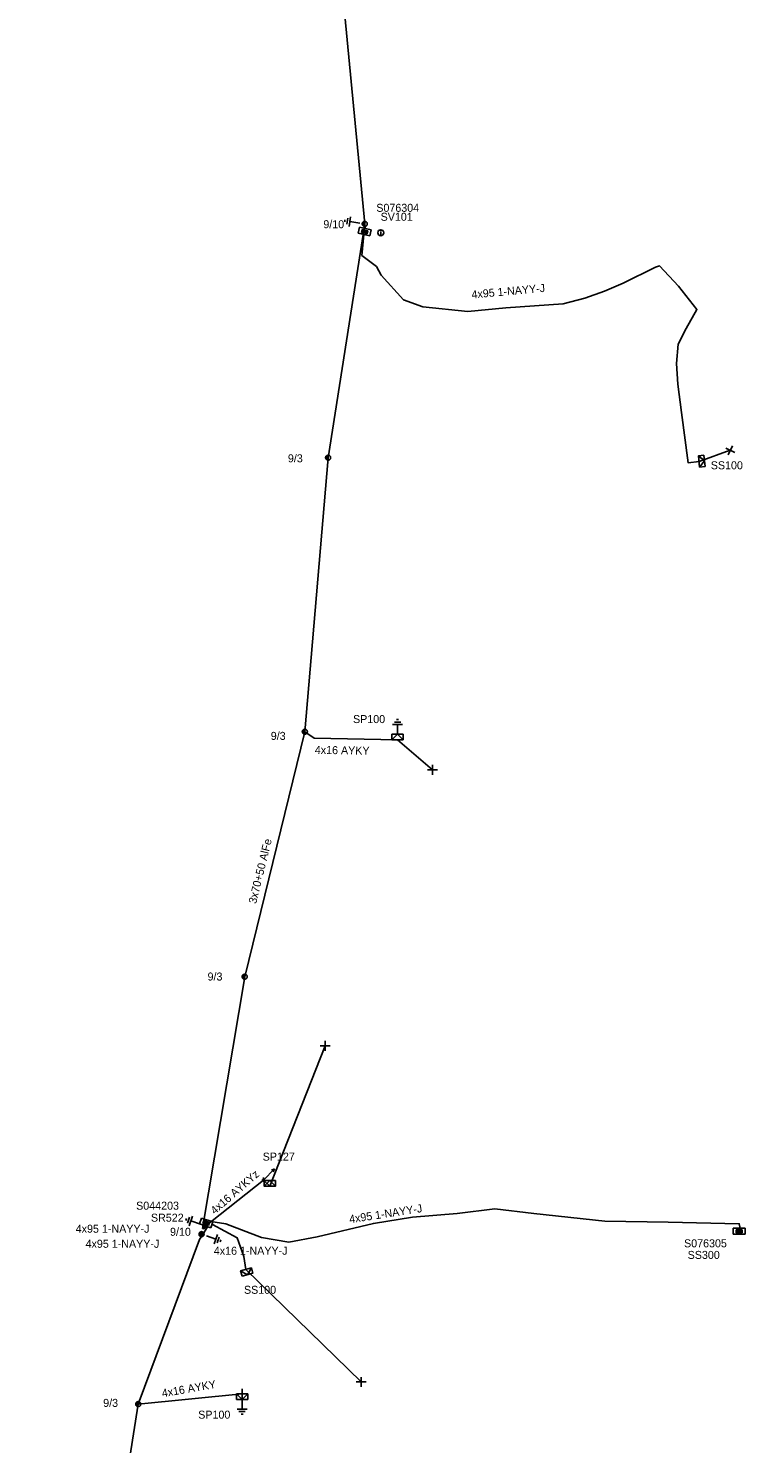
# Model space of a CAD drawing. Extents: x -717562 to -713845, y -1151196 to -1143903.
# Drawn here: x -714115 to -714025.6, y -1146849.6 to -1146672.7 of the extents above; entities that cross this region are included whole.
import ezdxf

# ---------------------------------------------------------------- set-up
doc = ezdxf.new("R2010")
doc.units = 0
for name, color, linetype in [('Vrstva 1', 7, 'Continuous'), ('Vrstva 10', 7, 'Continuous'), ('Vrstva 12', 7, 'Continuous'), ('Vrstva 13', 7, 'Continuous'), ('Vrstva 14', 7, 'Continuous'), ('Vrstva 15', 7, 'Continuous'), ('Vrstva 2', 7, 'Continuous'), ('Vrstva 28', 7, 'Continuous'), ('Vrstva 29', 7, 'Continuous'), ('Vrstva 30', 7, 'Continuous'), ('Vrstva 31', 7, 'Continuous'), ('Vrstva 33', 7, 'Continuous'), ('Vrstva 34', 7, 'Continuous'), ('Vrstva 36', 7, 'Continuous'), ('Vrstva 5', 7, 'Continuous'), ('Vrstva 52', 7, 'Continuous'), ('Vrstva 54', 7, 'Continuous'), ('Vrstva 55', 7, 'Continuous'), ('Vrstva 59', 7, 'Continuous'), ('Vrstva 6', 7, 'Continuous'), ('Vrstva 8', 7, 'Continuous'), ('Vrstva 9', 7, 'Continuous')]:
    doc.layers.add(name, color=color, linetype=linetype)

# ---------------------------------------------------------------- blocks, each defined once
blk = doc.blocks.new('NN440')
at = {"layer": 'Vrstva 2'}
for points in [[(0.63, 0), (0.63, 0.06), (0.62, 0.13), (0.6, 0.19), (0.58, 0.25), (0.55, 0.31), (0.51, 0.37), (0.47, 0.42), (0.42, 0.46), (0.37, 0.51), (0.32, 0.54), (0.26, 0.57), (0.2, 0.59), (0.13, 0.61), (0.07, 0.62), (0, 0.63), (-0.06, 0.62), (-0.13, 0.61), (-0.19, 0.59), (-0.26, 0.57), (-0.31, 0.54), (-0.37, 0.51), (-0.42, 0.46), (-0.47, 0.42), (-0.51, 0.37), (-0.54, 0.31), (-0.57, 0.25), (-0.6, 0.19), (-0.62, 0.13), (-0.63, 0.06), (-0.63, 0), (-0.63, -0.07), (-0.62, -0.14), (-0.6, -0.2), (-0.57, -0.26), (-0.54, -0.32), (-0.51, -0.37), (-0.47, -0.43), (-0.42, -0.47), (-0.37, -0.51), (-0.31, -0.55), (-0.26, -0.58), (-0.19, -0.6), (-0.13, -0.62), (-0.06, -0.63), (0, -0.63), (0.07, -0.63), (0.13, -0.62), (0.2, -0.6), (0.26, -0.58), (0.32, -0.55), (0.37, -0.51), (0.42, -0.47), (0.47, -0.43), (0.51, -0.37), (0.55, -0.32), (0.58, -0.26), (0.6, -0.2), (0.62, -0.14), (0.63, -0.07), (0.63, 0)], [(-0.63, 0), (0.63, 0)], [(-0.6, -0.18), (0.57, -0.18)], [(-0.51, -0.32), (0.5, -0.32)], [(-0.37, -0.47), (0.35, -0.47)]]:
    blk.add_lwpolyline(points, dxfattribs=at)
blk = doc.blocks.new('NN560')
at = {"layer": 'Vrstva 2'}
for points in [[(2, 0), (1.59, 0.14)], [(0, 0), (2, 0)], [(2, 0), (1.59, -0.13)]]:
    blk.add_lwpolyline(points, dxfattribs=at)
blk = doc.blocks.new('NN770')
at = {"layer": 'Vrstva 10'}
for p, q in [((0, 0.19), (0, 0.26)), ((0, -0.28), (0, 0.11))]:
    blk.add_line(p, q, dxfattribs=at)
blk.add_circle((0, -0.01), 0.375, dxfattribs=at)
blk = doc.blocks.new('NN800')
at = {"layer": 'Vrstva 1'}
for points in [[(-0.44, 0.44), (0.44, -0.44)], [(-0.44, -0.44), (0.44, 0.44)]]:
    blk.add_lwpolyline(points, dxfattribs=at)
blk = doc.blocks.new('NN620')
at = {"layer": 'Vrstva 8'}
for points in [[(0.75, 0), (-0.75, 0)], [(-0.75, 0), (-0.75, -0.75)], [(0.75, -0.75), (0.75, 0)], [(-0.75, -0.75), (0.75, -0.75)], [(0.37, -0.18), (-0.38, -0.18)], [(-0.38, -0.18), (-0.38, -0.56)], [(-0.38, -0.56), (0.37, -0.56)], [(0.32, -0.23), (-0.33, -0.23)], [(-0.33, -0.23), (-0.33, -0.51)], [(-0.33, -0.51), (0.32, -0.51)], [(0.27, -0.27), (-0.28, -0.27)], [(-0.28, -0.27), (-0.28, -0.46)], [(-0.28, -0.46), (0.27, -0.46)], [(0.23, -0.32), (-0.23, -0.32)], [(-0.23, -0.32), (-0.23, -0.42)], [(-0.23, -0.42), (0.23, -0.42)], [(-0.19, -0.37), (0.19, -0.37)], [(0.23, -0.42), (0.23, -0.32)], [(0.27, -0.46), (0.27, -0.27)], [(0.32, -0.51), (0.32, -0.23)], [(0.37, -0.56), (0.37, -0.18)]]:
    blk.add_lwpolyline(points, dxfattribs=at)
blk = doc.blocks.new('NN630')
at = {"layer": 'Vrstva 9'}
for points in [[(0, -0.7), (-0.7, 0)], [(-0.7, -0.7), (-0.7, 0), (0.7, 0), (0.7, -0.7)], [(-0.7, -0.7), (0.7, -0.7)], [(0, -0.7), (0.7, 0)]]:
    blk.add_lwpolyline(points, dxfattribs=at)
blk = doc.blocks.new('NN810')
at = {"layer": 'Vrstva 14'}
for points in [[(0, -0.64), (0, -1.89)], [(0.63, -1.89), (-0.62, -1.89)], [(0.39, -2.2), (-0.4, -2.2)], [(0, -2.52), (-0.12, -2.52)], [(0.14, -2.52), (0, -2.52)]]:
    blk.add_lwpolyline(points, dxfattribs=at)
blk = doc.blocks.new('NN500')
at = {"layer": 'Vrstva 2'}
for points in [[(0, -0.24), (0.02, -0.23), (0.05, -0.23), (0.07, -0.22), (0.09, -0.22), (0.12, -0.2), (0.14, -0.19), (0.16, -0.18), (0.17, -0.16), (0.19, -0.14), (0.2, -0.12), (0.21, -0.1), (0.22, -0.07), (0.23, -0.05), (0.23, -0.02), (0.23, 0), (0.23, 0.02), (0.23, 0.05), (0.22, 0.07), (0.21, 0.1), (0.2, 0.12), (0.19, 0.14), (0.17, 0.16), (0.16, 0.17), (0.14, 0.19), (0.12, 0.2), (0.09, 0.21), (0.07, 0.22), (0.05, 0.23), (0.02, 0.23), (0, 0.23), (-0.03, 0.23), (-0.05, 0.23), (-0.07, 0.22), (-0.1, 0.21), (-0.12, 0.2), (-0.14, 0.19), (-0.16, 0.17), (-0.18, 0.16), (-0.19, 0.14), (-0.2, 0.12), (-0.22, 0.1), (-0.22, 0.07), (-0.23, 0.05), (-0.23, 0.02), (-0.24, 0), (-0.23, -0.02), (-0.23, -0.05), (-0.22, -0.07), (-0.22, -0.1), (-0.2, -0.12), (-0.19, -0.14), (-0.18, -0.16), (-0.16, -0.18), (-0.14, -0.19), (-0.12, -0.2), (-0.1, -0.22), (-0.07, -0.22), (-0.05, -0.23), (-0.03, -0.23), (0, -0.24)], [(0, -0.24), (0.02, -0.23), (0.05, -0.23), (0.07, -0.22), (0.09, -0.22), (0.12, -0.2), (0.14, -0.19), (0.16, -0.18), (0.17, -0.16), (0.19, -0.14), (0.2, -0.12), (0.21, -0.1), (0.22, -0.07), (0.23, -0.05), (0.23, -0.02), (0.23, 0), (0.23, 0.02), (0.23, 0.05), (0.22, 0.07), (0.21, 0.1), (0.2, 0.12), (0.19, 0.14), (0.17, 0.16), (0.16, 0.17), (0.14, 0.19), (0.12, 0.2), (0.09, 0.21), (0.07, 0.22), (0.05, 0.23), (0.02, 0.23), (0, 0.23), (-0.03, 0.23), (-0.05, 0.23), (-0.07, 0.22), (-0.1, 0.21), (-0.12, 0.2), (-0.14, 0.19), (-0.16, 0.17), (-0.18, 0.16), (-0.19, 0.14), (-0.2, 0.12), (-0.22, 0.1), (-0.22, 0.07), (-0.23, 0.05), (-0.23, 0.02), (-0.24, 0), (-0.23, -0.02), (-0.23, -0.05), (-0.22, -0.07), (-0.22, -0.1), (-0.2, -0.12), (-0.19, -0.14), (-0.18, -0.16), (-0.16, -0.18), (-0.14, -0.19), (-0.12, -0.2), (-0.1, -0.22), (-0.07, -0.22), (-0.05, -0.23), (-0.03, -0.23), (0, -0.24)], [(0, -0.21), (0.02, -0.2), (0.04, -0.2), (0.06, -0.2), (0.08, -0.19), (0.1, -0.18), (0.12, -0.17), (0.14, -0.15), (0.15, -0.14), (0.16, -0.12), (0.18, -0.1), (0.19, -0.08), (0.19, -0.06), (0.2, -0.04), (0.2, -0.02), (0.2, 0), (0.2, 0.02), (0.2, 0.04), (0.19, 0.06), (0.19, 0.08), (0.18, 0.1), (0.16, 0.12), (0.15, 0.14), (0.14, 0.15), (0.12, 0.17), (0.1, 0.18), (0.08, 0.19), (0.06, 0.19), (0.04, 0.2), (0.02, 0.2), (0, 0.2), (-0.02, 0.2), (-0.04, 0.2), (-0.06, 0.19), (-0.08, 0.19), (-0.1, 0.18), (-0.12, 0.17), (-0.14, 0.15), (-0.15, 0.14), (-0.17, 0.12), (-0.18, 0.1), (-0.19, 0.08), (-0.2, 0.06), (-0.2, 0.04), (-0.21, 0.02), (-0.21, 0), (-0.21, -0.02), (-0.2, -0.04), (-0.2, -0.06), (-0.19, -0.08), (-0.18, -0.1), (-0.17, -0.12), (-0.15, -0.14), (-0.14, -0.15), (-0.12, -0.17), (-0.1, -0.18), (-0.08, -0.19), (-0.06, -0.2), (-0.04, -0.2), (-0.02, -0.2), (0, -0.21)], [(0, -0.18), (0.02, -0.18), (0.04, -0.17), (0.05, -0.17), (0.07, -0.16), (0.09, -0.15), (0.1, -0.14), (0.12, -0.13), (0.13, -0.12), (0.14, -0.1), (0.15, -0.09), (0.16, -0.07), (0.17, -0.05), (0.17, -0.04), (0.17, -0.02), (0.17, 0), (0.17, 0.02), (0.17, 0.04), (0.17, 0.05), (0.16, 0.07), (0.15, 0.09), (0.14, 0.1), (0.13, 0.12), (0.12, 0.13), (0.1, 0.14), (0.09, 0.15), (0.07, 0.16), (0.05, 0.17), (0.04, 0.17), (0.02, 0.17), (0, 0.18), (-0.02, 0.17), (-0.04, 0.17), (-0.06, 0.17), (-0.07, 0.16), (-0.09, 0.15), (-0.1, 0.14), (-0.12, 0.13), (-0.13, 0.12), (-0.14, 0.1), (-0.15, 0.09), (-0.16, 0.07), (-0.17, 0.05), (-0.17, 0.04), (-0.18, 0.02), (-0.18, 0), (-0.18, -0.02), (-0.17, -0.04), (-0.17, -0.05), (-0.16, -0.07), (-0.15, -0.09), (-0.14, -0.1), (-0.13, -0.12), (-0.12, -0.13), (-0.1, -0.14), (-0.09, -0.15), (-0.07, -0.16), (-0.06, -0.17), (-0.04, -0.17), (-0.02, -0.18), (0, -0.18)], [(0, -0.15), (0.01, -0.15), (0.03, -0.14), (0.04, -0.14), (0.06, -0.13), (0.07, -0.13), (0.08, -0.12), (0.1, -0.11), (0.11, -0.1), (0.12, -0.09), (0.13, -0.07), (0.13, -0.06), (0.14, -0.05), (0.14, -0.03), (0.14, -0.02), (0.14, 0), (0.14, 0.01), (0.14, 0.03), (0.14, 0.04), (0.13, 0.06), (0.13, 0.07), (0.12, 0.09), (0.11, 0.1), (0.1, 0.11), (0.08, 0.12), (0.07, 0.13), (0.06, 0.13), (0.04, 0.14), (0.03, 0.14), (0.01, 0.14), (0, 0.15), (-0.02, 0.14), (-0.03, 0.14), (-0.05, 0.14), (-0.06, 0.13), (-0.07, 0.13), (-0.09, 0.12), (-0.1, 0.11), (-0.11, 0.1), (-0.12, 0.09), (-0.13, 0.07), (-0.13, 0.06), (-0.14, 0.04), (-0.14, 0.03), (-0.15, 0.01), (-0.15, 0), (-0.15, -0.02), (-0.14, -0.03), (-0.14, -0.05), (-0.13, -0.06), (-0.13, -0.07), (-0.12, -0.09), (-0.11, -0.1), (-0.1, -0.11), (-0.09, -0.12), (-0.07, -0.13), (-0.06, -0.13), (-0.05, -0.14), (-0.03, -0.14), (-0.02, -0.15), (0, -0.15)], [(0, -0.12), (0.01, -0.12), (0.02, -0.11), (0.03, -0.11), (0.05, -0.11), (0.06, -0.1), (0.07, -0.09), (0.08, -0.09), (0.09, -0.08), (0.09, -0.07), (0.1, -0.06), (0.11, -0.05), (0.11, -0.04), (0.11, -0.02), (0.11, -0.01), (0.12, 0), (0.11, 0.01), (0.11, 0.02), (0.11, 0.04), (0.11, 0.05), (0.1, 0.06), (0.09, 0.07), (0.09, 0.08), (0.08, 0.09), (0.07, 0.09), (0.06, 0.1), (0.05, 0.11), (0.03, 0.11), (0.02, 0.11), (0.01, 0.12), (0, 0.12), (-0.01, 0.12), (-0.03, 0.11), (-0.04, 0.11), (-0.05, 0.11), (-0.06, 0.1), (-0.07, 0.09), (-0.08, 0.09), (-0.09, 0.08), (-0.1, 0.07), (-0.1, 0.06), (-0.11, 0.05), (-0.11, 0.04), (-0.12, 0.02), (-0.12, 0.01), (-0.12, 0), (-0.12, -0.01), (-0.12, -0.02), (-0.11, -0.04), (-0.11, -0.05), (-0.1, -0.06), (-0.1, -0.07), (-0.09, -0.08), (-0.08, -0.09), (-0.07, -0.09), (-0.06, -0.1), (-0.05, -0.11), (-0.04, -0.11), (-0.03, -0.11), (-0.01, -0.12), (0, -0.12)], [(0, -0.09), (0.01, -0.09), (0.02, -0.09), (0.03, -0.08), (0.03, -0.08), (0.04, -0.08), (0.05, -0.07), (0.06, -0.07), (0.06, -0.06), (0.07, -0.05), (0.07, -0.04), (0.08, -0.04), (0.08, -0.03), (0.08, -0.02), (0.09, -0.01), (0.09, 0), (0.09, 0.01), (0.08, 0.02), (0.08, 0.03), (0.08, 0.03), (0.07, 0.04), (0.07, 0.05), (0.06, 0.06), (0.06, 0.06), (0.05, 0.07), (0.04, 0.07), (0.03, 0.08), (0.03, 0.08), (0.02, 0.08), (0.01, 0.09), (0, 0.09), (-0.01, 0.09), (-0.02, 0.08), (-0.03, 0.08), (-0.04, 0.08), (-0.04, 0.07), (-0.05, 0.07), (-0.06, 0.06), (-0.07, 0.06), (-0.07, 0.05), (-0.08, 0.04), (-0.08, 0.03), (-0.08, 0.03), (-0.09, 0.02), (-0.09, 0.01), (-0.09, 0), (-0.09, -0.01), (-0.09, -0.02), (-0.08, -0.03), (-0.08, -0.04), (-0.08, -0.04), (-0.07, -0.05), (-0.07, -0.06), (-0.06, -0.07), (-0.05, -0.07), (-0.04, -0.08), (-0.04, -0.08), (-0.03, -0.08), (-0.02, -0.09), (-0.01, -0.09), (0, -0.09)], [(0, -0.06), (0, -0.06), (0.01, -0.06), (0.02, -0.05), (0.02, -0.05), (0.03, -0.05), (0.03, -0.05), (0.04, -0.04), (0.04, -0.04), (0.05, -0.03), (0.05, -0.03), (0.05, -0.02), (0.05, -0.02), (0.05, -0.01), (0.06, -0.01), (0.06, 0), (0.06, 0.01), (0.05, 0.01), (0.05, 0.02), (0.05, 0.02), (0.05, 0.03), (0.05, 0.03), (0.04, 0.04), (0.04, 0.04), (0.03, 0.05), (0.03, 0.05), (0.02, 0.05), (0.02, 0.05), (0.01, 0.06), (0, 0.06), (0, 0.06), (-0.01, 0.06), (-0.01, 0.06), (-0.02, 0.05), (-0.02, 0.05), (-0.03, 0.05), (-0.03, 0.05), (-0.04, 0.04), (-0.04, 0.04), (-0.05, 0.03), (-0.05, 0.03), (-0.05, 0.02), (-0.06, 0.02), (-0.06, 0.01), (-0.06, 0.01), (-0.06, 0), (-0.06, -0.01), (-0.06, -0.01), (-0.06, -0.02), (-0.05, -0.02), (-0.05, -0.03), (-0.05, -0.03), (-0.04, -0.04), (-0.04, -0.04), (-0.03, -0.05), (-0.03, -0.05), (-0.02, -0.05), (-0.02, -0.05), (-0.01, -0.06), (-0.01, -0.06), (0, -0.06)], [(0, -0.03), (0, -0.03), (0, -0.03), (0.01, -0.03), (0.01, -0.03), (0.01, -0.02), (0.02, -0.02), (0.02, -0.02), (0.02, -0.02), (0.02, -0.02), (0.02, -0.01), (0.02, -0.01), (0.03, -0.01), (0.03, -0.01), (0.03, 0), (0.03, 0), (0.03, 0), (0.03, 0.01), (0.03, 0.01), (0.02, 0.01), (0.02, 0.01), (0.02, 0.02), (0.02, 0.02), (0.02, 0.02), (0.02, 0.02), (0.01, 0.02), (0.01, 0.02), (0.01, 0.03), (0, 0.03), (0, 0.03), (0, 0.03), (0, 0.03), (-0.01, 0.03), (-0.01, 0.03), (-0.01, 0.02), (-0.02, 0.02), (-0.02, 0.02), (-0.02, 0.02), (-0.02, 0.02), (-0.02, 0.02), (-0.03, 0.01), (-0.03, 0.01), (-0.03, 0.01), (-0.03, 0.01), (-0.03, 0), (-0.03, 0), (-0.03, 0), (-0.03, -0.01), (-0.03, -0.01), (-0.03, -0.01), (-0.03, -0.01), (-0.02, -0.02), (-0.02, -0.02), (-0.02, -0.02), (-0.02, -0.02), (-0.02, -0.02), (-0.01, -0.03), (-0.01, -0.03), (-0.01, -0.03), (0, -0.03), (0, -0.03)], [(0.23, 0), (0.7, 0)]]:
    blk.add_lwpolyline(points, dxfattribs=at)

msp = doc.modelspace()

# ---------------------------------------------------------------- linework, layer by layer
at = {"layer": 'Vrstva 1'}
for points in [[(-714072.98, -1146697.18), (-714076.4, -1146661.55), (-714072.51, -1146633.47)], [(-714093.26, -1146822.72), (-714087.99, -1146791.24), (-714080.47, -1146760.63), (-714077.56, -1146726.39), (-714072.98, -1146697.18)], [(-714115.04, -1146895.35), (-714105, -1146868.24), (-714101.3, -1146844.64), (-714093.62, -1146824.06)]]:
    msp.add_lwpolyline(points, dxfattribs=at)
at = {"layer": 'Vrstva 5'}
for points in [[(-714073.09, -1146698.49), (-714073.33, -1146701.12), (-714071.5, -1146702.52), (-714070.94, -1146703.6), (-714068.15, -1146706.65), (-714065.71, -1146707.54), (-714060.11, -1146708.11), (-714055.34, -1146707.67), (-714048.2, -1146707.15), (-714045.47, -1146706.44), (-714043, -1146705.6), (-714040.68, -1146704.59), (-714036.63, -1146702.59), (-714036.15, -1146702.43), (-714033.75, -1146704.95), (-714031.47, -1146707.86), (-714032.82, -1146710.23), (-714033.8, -1146712.2), (-714034.02, -1146714.64), (-714033.84, -1146717.22), (-714033.38, -1146720.73), (-714032.57, -1146727.02), (-714031.2, -1146726.86)], [(-714072.98, -1146697.18), (-714072.91, -1146697.82)], [(-714092.22, -1146821.82), (-714090.35, -1146822.1), (-714085.87, -1146823.83), (-714082.47, -1146824.4), (-714078.93, -1146823.74), (-714071.9, -1146822.06), (-714067, -1146821.3), (-714061.42, -1146820.84), (-714056.71, -1146820.25), (-714051.83, -1146820.84), (-714042.98, -1146821.78), (-714035.07, -1146821.89), (-714026.18, -1146822.1), (-714026.05, -1146822.67)], [(-714093.62, -1146824.06), (-714093.24, -1146823.45), (-714092.63, -1146822.49)], [(-714093.26, -1146822.72), (-714093.09, -1146822.75), (-714092.77, -1146822.45)], [(-714092.01, -1146822.21), (-714088.92, -1146823.85), (-714088.11, -1146826.2), (-714087.83, -1146827.81)]]:
    msp.add_lwpolyline(points, dxfattribs=at)
at = {"layer": 'Vrstva 52'}
for points in [[(-714080.47, -1146760.63), (-714079.31, -1146761.45), (-714068.89, -1146761.63)], [(-714101.3, -1146844.64), (-714088.31, -1146843.37)]]:
    msp.add_lwpolyline(points, dxfattribs=at)
at = {"layer": 'Vrstva 54'}
msp.add_lwpolyline([(-714093.26, -1146822.72), (-714085.65, -1146816.66), (-714084.85, -1146817.42)], dxfattribs=at)
at = {"layer": 'Vrstva 59'}
for points in [[(-714031.2, -1146726.86), (-714027.29, -1146725.47)], [(-714068.89, -1146761.63), (-714064.5, -1146765.38)], [(-714084.85, -1146817.42), (-714077.94, -1146799.88)], [(-714087.83, -1146827.81), (-714073.44, -1146841.88)]]:
    msp.add_lwpolyline(points, dxfattribs=at)

# ---------------------------------------------------------------- block references
at = {"layer": 'Vrstva 13'}
for name, p, xscale, yscale, rotation in [('NN440', (-714072.98, -1146697.18), 0.5000000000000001, 0.5, -98.74915832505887), ('NN440', (-714077.56, -1146726.39), 0.5000000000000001, 0.4999999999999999, -98.74915834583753), ('NN440', (-714080.47, -1146760.63), 0.5000000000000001, 0.4999999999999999, -98.74915834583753), ('NN440', (-714087.99, -1146791.24), 0.5000000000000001, 0.5, -98.74915832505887), ('NN500', (-714085.65, -1146816.66), 0.5, 0.5, 90), ('NN440', (-714093.38, -1146823.41), 0.5, 0.5, -109.21066662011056), ('NN440', (-714101.3, -1146844.64), 0.5, 0.5, -109.21066662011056)]:
    msp.add_blockref(name, p, dxfattribs=dict(at, xscale=xscale, yscale=yscale, rotation=rotation))
at = {"layer": 'Vrstva 13', "rotation": 45.7040289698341}
msp.add_blockref('NN560', (-714085.65, -1146816.66), dxfattribs=at)
at = {"layer": 'Vrstva 15'}
for p, rotation in [((-714072.98, -1146697.18), -98.74915832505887), ((-714068.89, -1146761.63), 180), ((-714092.92, -1146822.36), -108.5969527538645), ((-714093.38, -1146823.41), 70.78933333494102)]:
    msp.add_blockref('NN810', p, dxfattribs=dict(at, rotation=rotation))
msp.add_blockref('NN810', (-714088.31, -1146843.37), dxfattribs=at)
at = {"layer": 'Vrstva 28'}
for p, rotation in [((-714073.07, -1146698.5), 167.58313940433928), ((-714092.92, -1146822.36), 161.4030471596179)]:
    msp.add_blockref('NN620', p, dxfattribs=dict(at, rotation=rotation))
msp.add_blockref('NN620', (-714026.16, -1146822.67), dxfattribs=at)
at = {"layer": 'Vrstva 31'}
for p, rotation in [((-714031.2, -1146726.86), 96.66130172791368), ((-714068.89, -1146761.63), 180), ((-714084.85, -1146817.42), 180), ((-714087.83, -1146827.81), 15.871244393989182)]:
    msp.add_blockref('NN630', p, dxfattribs=dict(at, rotation=rotation))
msp.add_blockref('NN630', (-714088.31, -1146843.37), dxfattribs=at)
at = {"layer": 'Vrstva 34'}
for p, rotation in [((-714027.29, -1146725.47), 19.527996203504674), ((-714064.5, -1146765.38), 45), ((-714077.94, -1146799.88), 44.99999995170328), ((-714073.44, -1146841.88), 44.99999995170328), ((-714088.31, -1146843.37), 45)]:
    msp.add_blockref('NN800', p, dxfattribs=dict(at, rotation=rotation))
at = {"layer": 'Vrstva 36'}
msp.add_blockref('NN770', (-714070.98, -1146698.28), dxfattribs=at)

# ---------------------------------------------------------------- texts
at = {"layer": 'Vrstva 12'}
for s, p in [('9/10', (-714078.16, -1146697.72)), ('9/3', (-714082.59, -1146726.97)), ('9/3', (-714084.73, -1146761.65)), ('9/3', (-714092.63, -1146791.72)), ('9/10', (-714097.32, -1146823.61)), ('9/3', (-714105.68, -1146844.99))]:
    msp.add_text(s, height=1, dxfattribs=at).set_placement(p)
at = {"layer": 'Vrstva 2'}
msp.add_text('3x70+50 AlFe', height=1, rotation=76.205, dxfattribs=at).set_placement((-714086.56, -1146782.19))
at = {"layer": 'Vrstva 29'}
for s, p in [('S076304', (-714071.54, -1146695.67)), ('S044203', (-714101.56, -1146820.35)), ('S076305', (-714033.07, -1146825.05))]:
    msp.add_text(s, height=1, dxfattribs=at).set_placement(p)
at = {"layer": 'Vrstva 30'}
for s, p in [('SV101', (-714071, -1146696.79)), ('SR522', (-714099.71, -1146821.85)), ('SS300', (-714032.62, -1146826.5))]:
    msp.add_text(s, height=1, dxfattribs=at).set_placement(p)
at = {"layer": 'Vrstva 33'}
for s, p in [('SS100', (-714029.73, -1146727.84)), ('SP100', (-714074.45, -1146759.55)), ('SP127', (-714085.74, -1146814.22)), ('SS100', (-714088.08, -1146830.86)), ('SP100', (-714093.8, -1146846.46))]:
    msp.add_text(s, height=1, dxfattribs=at).set_placement(p)
at = {"layer": 'Vrstva 54'}
for rotation, p in [(359.016, (-714079.23, -1146763.39)), (9.918, (-714098.26, -1146843.79))]:
    msp.add_text('4x16 AYKY', height=1, rotation=rotation, dxfattribs=at).set_placement(p)
at = {"layer": 'Vrstva 55'}
msp.add_text('4x16 AYKYz', height=1, rotation=41.128, dxfattribs=at).set_placement((-714091.73, -1146820.99))
at = {"layer": 'Vrstva 6'}
for rotation, p in [(5.27, (-714059.59, -1146706.51)), (8.816, (-714074.85, -1146822.05))]:
    msp.add_text('4x95 1-NAYY-J', height=1, rotation=rotation, dxfattribs=at).set_placement(p)
for s, p in [('4x95 1-NAYY-J', (-714109.11, -1146823.23)), ('4x95 1-NAYY-J', (-714107.88, -1146825.11)), ('4x16 1-NAYY-J', (-714091.85, -1146825.98))]:
    msp.add_text(s, height=1, dxfattribs=at).set_placement(p)

doc.saveas('drawing.dxf')
